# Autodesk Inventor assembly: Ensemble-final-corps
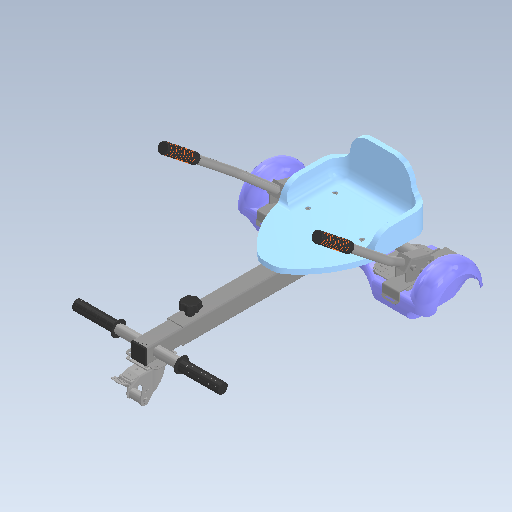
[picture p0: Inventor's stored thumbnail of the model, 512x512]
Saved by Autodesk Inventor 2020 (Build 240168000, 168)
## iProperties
Created: 2022-10
Part Number: Ensemble-final-corps
Document SubType Name: Assembly
Designer: bruno
Mass: 7492 g
Surface Area: 14882.5 cm^2
Volume: 7492 cm^3
Density: 1 g/cm^3
Author: bruno
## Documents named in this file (5)
- C:\Users\bruno\Documents\1-Cours-2022-23\1SI\2. Cinématique\Hoverboard\Inventor-Hoverboard\Ensemble-final-corps.iam
- C:\Users\bruno\Documents\1-Cours-2022-23\1SI\2. Cinématique\Hoverboard\Inventor-Hoverboard\hover2.iam
- C:\Users\bruno\Documents\1-Cours-2022-23\1SI\2. Cinématique\Hoverboard\Inventor-Hoverboard\Tube-carre-2.ipt
- C:\Users\bruno\Documents\1-Cours-2022-23\1SI\2. Cinématique\Hoverboard\Inventor-Hoverboard\Hoverboard.ipt
- C:\Users\bruno\Documents\1-Cours-2022-23\1SI\2. Cinématique\Hoverboard\Inventor-Hoverboard\LKPA-VPA 101K-FI.ipt
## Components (4 placed, 4 different names)
1. hover2:1 [sub-assembly] — Placage:1, Placage:2, Placage:3, Placage:4, Placage:5, Placage:6, Affleurement:1, Affleurement:2
2. Tube-carre-2:1 — Placage:1, Placage:2
3. Hoverboard:1 — Placage:3, Placage:4, Placage:5
4. LKPA-VPA 101K-FI:1 — Placage:6, Affleurement:1, Affleurement:2
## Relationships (8: Mate 6, Flush 2)
- Placage:1 [Mate]: hover2:1 ↔ Tube-carre-2:1
- Placage:2 [Mate]: hover2:1 ↔ Tube-carre-2:1
- Placage:3 [Mate]: hover2:1 ↔ Hoverboard:1
- Placage:4 [Mate]: hover2:1 ↔ Hoverboard:1
- Placage:5 [Mate]: hover2:1 ↔ Hoverboard:1
- Placage:6 [Mate]: hover2:1 ↔ LKPA-VPA 101K-FI:1
- Affleurement:1 [Flush]: hover2:1 ↔ LKPA-VPA 101K-FI:1
- Affleurement:2 [Flush]: hover2:1 ↔ LKPA-VPA 101K-FI:1
